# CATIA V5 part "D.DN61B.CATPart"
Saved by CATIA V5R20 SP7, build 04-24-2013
Part number: D.DN61B
Material "Nessuno"
Bounding box of the stored display mesh (mm): x 0 to 150.807, y -135.185 to 0, z -91.151 to 75.737
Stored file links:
  C:\Users\designer2\Desktop\Ottobre 2022\25-10-2022\04\Yori Evo 48V\D.DN61B.CATPart
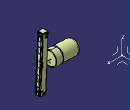
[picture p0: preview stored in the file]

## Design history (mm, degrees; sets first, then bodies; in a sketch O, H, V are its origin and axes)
AxisSystem1: origin (0, 0, 0), X (1, 0, 0), Y (0, 1, 0), Z (0, 0, 1)
Set1
  DatumSurface1
Body1 (main body), material "Nessuno"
